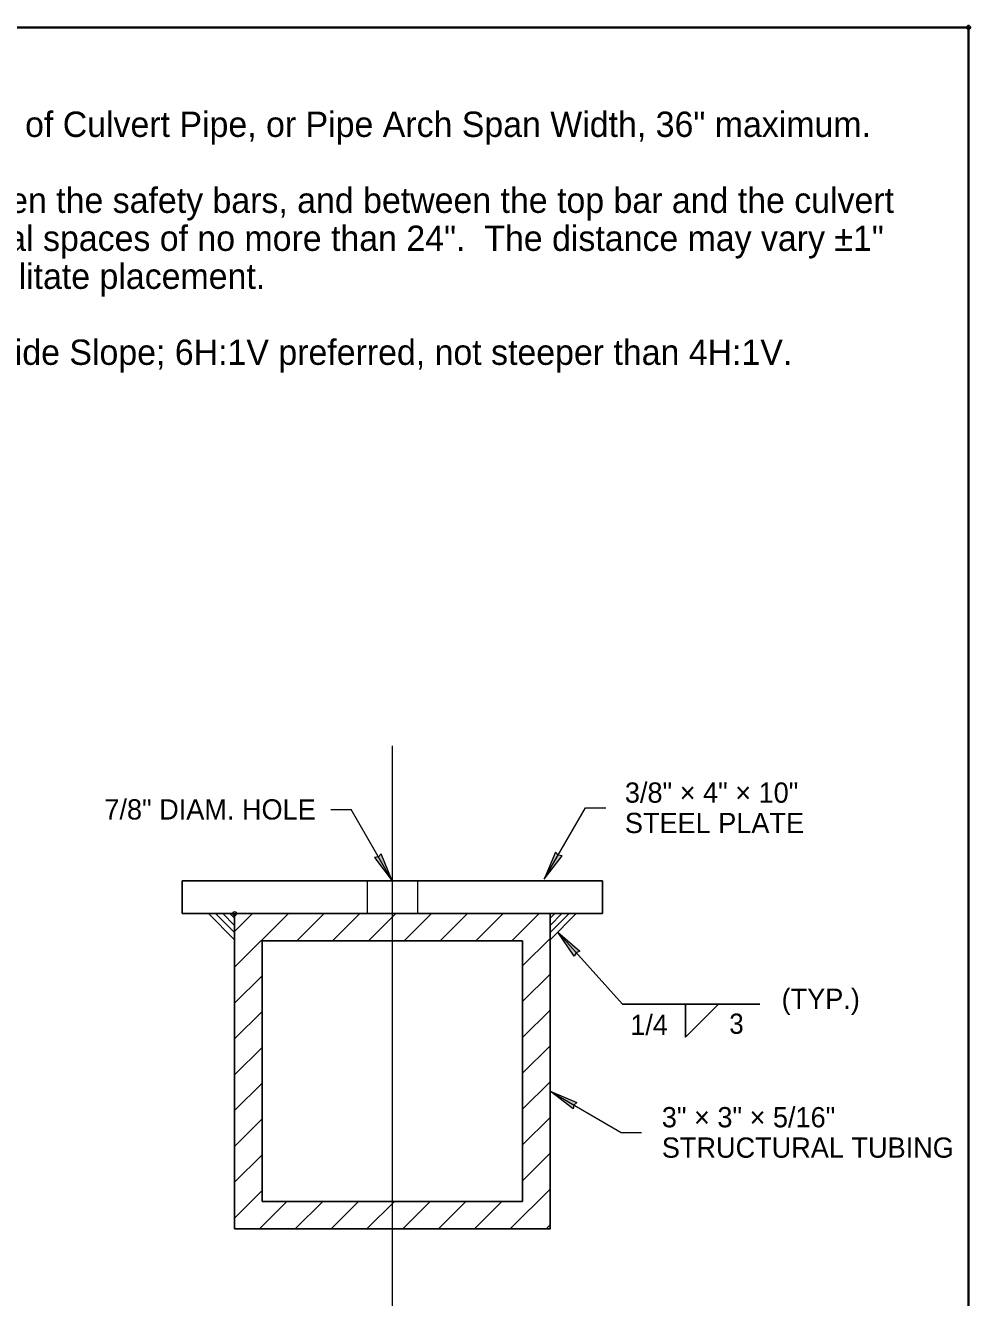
# Model space of a CAD drawing. Extents: x 99860 to 103153, y 99998 to 102077.
# Drawn here: x 102406 to 103153, y 101073 to 102077 of the extents above; entities that cross this region are included whole.
import ezdxf
from ezdxf.enums import TextEntityAlignment as Align

# ---------------------------------------------------------------- set-up
doc = ezdxf.new("R2010")
doc.units = 0
doc.header["$LTSCALE"] = 6.4
doc.header["$PDMODE"] = 32
doc.header["$PDSIZE"] = 3.2
for name, color, linetype, lineweight in [('1', 7, 'Continuous', 13), ('15', 7, 'Continuous', 13), ('2', 7, 'Continuous', 13), ('20', 7, 'Continuous', 13), ('22', 7, 'Continuous', 25), ('36', 7, 'Continuous', 13)]:
    doc.layers.add(name, color=color, linetype=linetype, lineweight=lineweight)
doc.layers.add('60', color=7, linetype='Continuous')

msp = doc.modelspace()

# ---------------------------------------------------------------- hatches: boundary and pattern name
at = {"layer": '15'}
for points in [[(102695.963, 101401.724), (102687.133, 101422.987), (102685.076, 101420.58), (102681.963, 101420.002)], [(102815.979, 101402.985), (102829.978, 101421.263), (102826.864, 101421.839), (102824.808, 101424.248)], [(102826.607, 101361.087), (102844.07, 101346.084), (102841.143, 101344.877), (102839.626, 101342.098)], [(102820.493, 101235.454), (102841.756, 101226.624), (102839.349, 101224.567), (102838.771, 101221.454)]]:
    msp.add_hatch(color=256, dxfattribs=at).paths.add_polyline_path(points)

# ---------------------------------------------------------------- linework, layer by layer
at = {"layer": '1', "lineweight": 25}
for p, q in [((102529.963, 101401.724), (102529.963, 101375.774)), ((102529.963, 101401.724), (102861.963, 101401.724)), ((102861.963, 101401.724), (102861.963, 101375.774)), ((102529.963, 101375.774), (102861.963, 101375.774)), ((102593.058, 101354.149), (102798.868, 101354.149)), ((102593.058, 101148.339), (102593.058, 101354.149)), ((102798.868, 101148.339), (102798.868, 101354.149)), ((102593.058, 101148.339), (102798.868, 101148.339))]:
    msp.add_line(p, q, dxfattribs=at)
at = {"layer": '1', "lineweight": 35}
msp.add_lwpolyline([(99862, 99999.5), (103151, 99999.5), (103151, 102075.5), (99862, 102075.5)], close=True, dxfattribs=at)
at = {"layer": '1', "lineweight": 25}
for points in [[(102571.433, 101126.714), (102820.493, 101126.714), (102820.493, 101375.774)], [(102571.433, 101126.714), (102571.433, 101375.774), (102820.493, 101375.774)]]:
    msp.add_lwpolyline(points, dxfattribs=at)
at = {"layer": '15'}
for p, q in [((102695.963, 101508.243), (102695.963, 101060.487)), ((102647.463, 101458.015), (102663.463, 101458.015)), ((102695.963, 101401.724), (102663.463, 101458.015)), ((102815.978, 101402.985), (102848.478, 101459.277)), ((102848.479, 101459.277), (102864.479, 101459.277)), ((102877.677, 101304.137), (102826.607, 101361.087)), ((102820.491, 101235.453), (102876.783, 101202.953)), ((102876.783, 101202.954), (102892.783, 101202.954))]:
    msp.add_line(p, q, dxfattribs=at)
at = {"layer": '15', "lineweight": 25}
for p, q in [((102877.677, 101304.137), (102986.189, 101304.137)), ((102927.56, 101278.127), (102927.56, 101304.137)), ((102927.56, 101278.127), (102953.57, 101304.137))]:
    msp.add_line(p, q, dxfattribs=at)
at = {"layer": '15'}
for points in [[(102695.963, 101401.724), (102687.133, 101422.987), (102685.076, 101420.58), (102681.963, 101420.002)], [(102815.979, 101402.985), (102829.978, 101421.263), (102826.864, 101421.839), (102824.808, 101424.248)], [(102826.607, 101361.087), (102844.07, 101346.084), (102841.143, 101344.877), (102839.626, 101342.098)], [(102820.493, 101235.454), (102841.756, 101226.624), (102839.349, 101224.567), (102838.771, 101221.454)]]:
    msp.add_lwpolyline(points, close=True, dxfattribs=at)
at = {"layer": '2'}
for p, q in [((102571.433, 101361.632), (102585.575, 101375.774)), ((102571.433, 101333.347), (102613.859, 101375.774)), ((102620.519, 101354.149), (102642.144, 101375.774)), ((102648.803, 101354.149), (102670.428, 101375.774)), ((102677.087, 101354.149), (102698.712, 101375.774)), ((102705.372, 101354.149), (102726.997, 101375.774)), ((102733.656, 101354.149), (102755.281, 101375.774)), ((102761.94, 101354.149), (102783.565, 101375.774)), ((102790.224, 101354.149), (102811.849, 101375.774)), ((102798.868, 101334.508), (102820.493, 101356.133)), ((102571.433, 101305.063), (102593.058, 101326.688)), ((102798.868, 101306.224), (102820.493, 101327.849)), ((102571.433, 101276.779), (102593.058, 101298.404)), ((102798.868, 101277.94), (102820.493, 101299.565)), ((102798.868, 101249.655), (102820.493, 101271.28)), ((102571.433, 101248.494), (102593.058, 101270.119)), ((102571.433, 101220.21), (102593.058, 101241.835)), ((102798.868, 101221.371), (102820.493, 101242.996)), ((102571.433, 101191.926), (102593.058, 101213.551)), ((102798.868, 101193.087), (102820.493, 101214.712)), ((102571.433, 101163.642), (102593.058, 101185.267)), ((102798.868, 101164.802), (102820.493, 101186.427)), ((102571.433, 101135.357), (102593.058, 101156.982)), ((102789.064, 101126.714), (102820.493, 101158.143)), ((102591.074, 101126.714), (102612.699, 101148.339)), ((102619.358, 101126.714), (102640.983, 101148.339)), ((102647.642, 101126.714), (102669.267, 101148.339)), ((102675.926, 101126.714), (102697.551, 101148.339)), ((102704.211, 101126.714), (102725.836, 101148.339)), ((102732.495, 101126.714), (102754.12, 101148.339)), ((102760.779, 101126.714), (102782.404, 101148.339)), ((102817.348, 101126.714), (102820.493, 101129.859))]:
    msp.add_line(p, q, dxfattribs=at)
msp.add_point((102571.433, 101375.774), dxfattribs=at)
at = {"layer": '22'}
for p, q in [((102550.698, 101375.774), (102571.433, 101355.039)), ((102556.355, 101375.774), (102571.433, 101360.696)), ((102562.012, 101375.774), (102571.433, 101366.352)), ((102567.669, 101375.774), (102571.433, 101372.009)), ((102841.228, 101375.774), (102820.493, 101355.039)), ((102835.571, 101375.774), (102820.493, 101360.696)), ((102829.914, 101375.774), (102820.493, 101366.352)), ((102824.258, 101375.774), (102820.493, 101372.009))]:
    msp.add_line(p, q, dxfattribs=at)
at = {"layer": '36'}
for p, q in [((102675.963, 101401.724), (102675.963, 101375.774)), ((102715.963, 101401.724), (102715.963, 101375.774))]:
    msp.add_line(p, q, dxfattribs=at)
at = {"layer": '60'}
msp.add_point((103151, 102075.5), dxfattribs=at)

# ---------------------------------------------------------------- texts
at = {"layer": '20'}
for s, height, p in [('D = Inside Diameter of Culvert Pipe, or Pipe Arch Span Width, 36" maximum.', 20, (102161.444, 101989.052)), ('The distance between the safety bars, and between the top bar and the culvert', 20, (102161.444, 101929.052)), ('crown, shall be equal spaces of no more than 24".  The distance may vary ±1"', 20, (102161.444, 101899.052)), ('between bars to facilitate placement.', 20, (102161.444, 101869.052)), ('Slope shall match Side Slope; 6H:1V preferred, not steeper than 4H:1V.', 20, (102161.444, 101809.052)), ('3/8" × 4" × 10"', 16, (102879.615, 101463.308)), ('STEEL PLATE', 16, (102879.615, 101439.308)), ('(TYP.)', 16, (103003.383, 101300.489)), (' 1/4 ', 16, (102877.905, 101279.882)), ('3" × 3" × 5/16"', 16, (102908.783, 101206.954)), ('STRUCTURAL TUBING', 16, (102908.783, 101182.954))]:
    msp.add_text(s, height=height, dxfattribs=at).set_placement(p)
msp.add_text('7/8" DIAM. HOLE', height=16, dxfattribs=at).set_placement((102635.474, 101450.017), align=Align.RIGHT)
at = {"layer": '20', "width": 0.95}
msp.add_text('3', height=16, dxfattribs=at).set_placement((102962.099, 101280.812))

doc.saveas('drawing.dxf')
